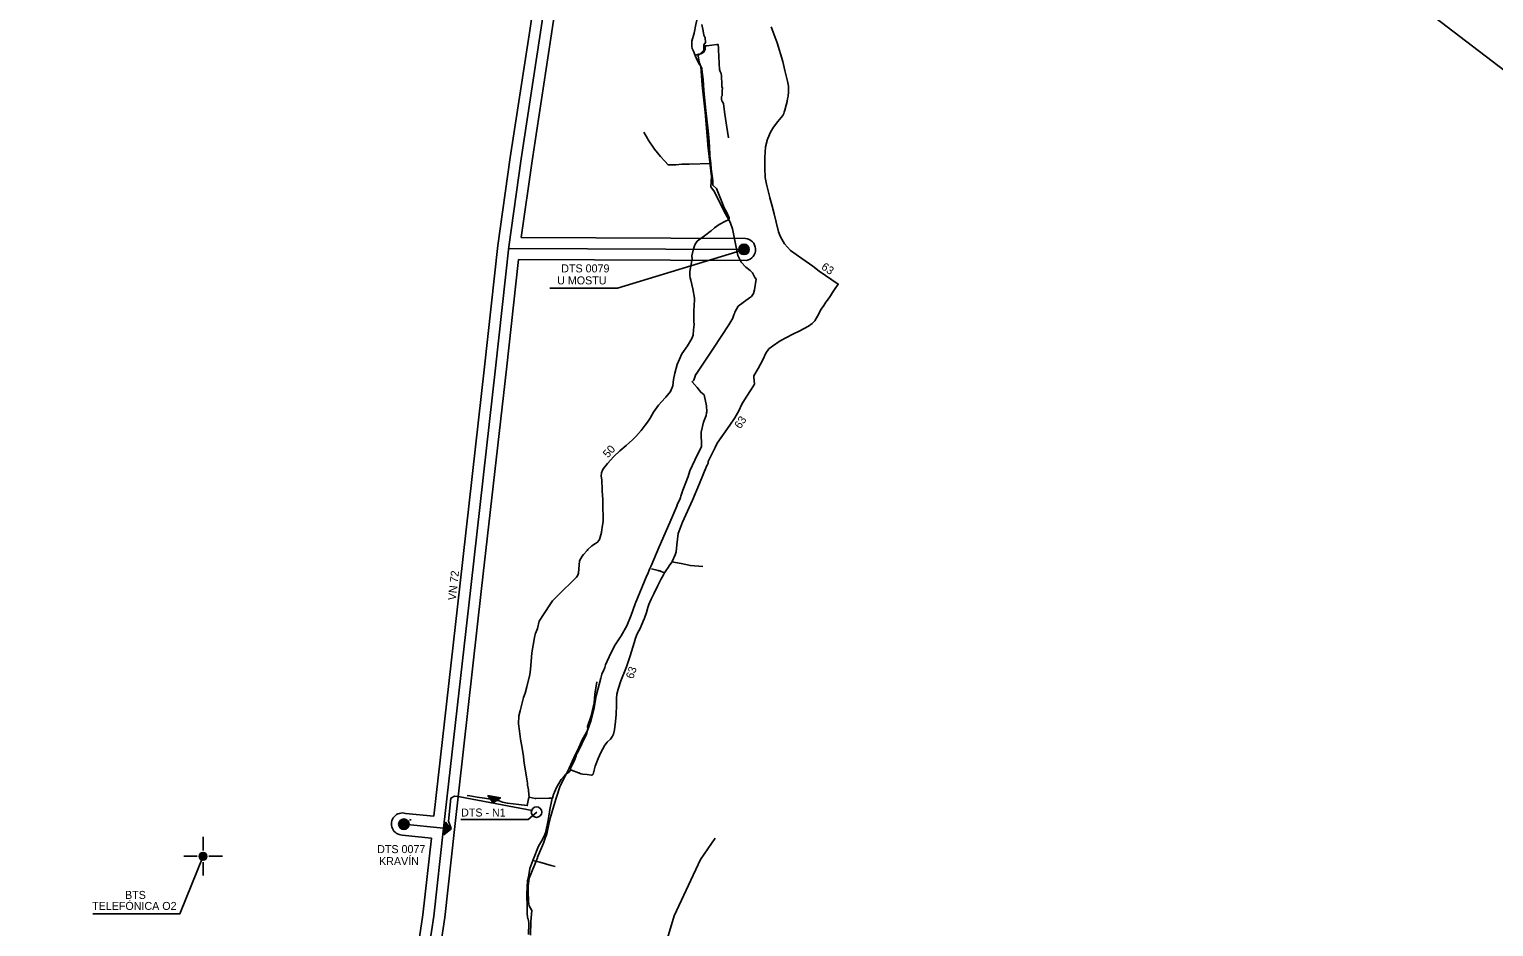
# Model space of a CAD drawing. Extents: x -545241 to -532622, y -1042837 to -1037240.
# Drawn here: x -543118 to -541654, y -1039462 to -1038564 of the extents above; entities that cross this region are included whole.
import ezdxf

# ---------------------------------------------------------------- set-up
doc = ezdxf.new("R2010")
doc.units = 0
for name, color, linetype in [('Vrstva 11', 7, 'Continuous'), ('Vrstva 12', 7, 'Continuous'), ('Vrstva 16', 7, 'Continuous'), ('Vrstva 18', 7, 'Continuous'), ('Vrstva 29', 7, 'Continuous'), ('Vrstva 33', 7, 'Continuous'), ('Vrstva 35', 7, 'Continuous'), ('Vrstva 38', 7, 'Continuous'), ('Vrstva 58', 7, 'Continuous'), ('Vrstva 59', 7, 'Continuous'), ('Vrstva 6', 7, 'Continuous'), ('Vrstva 60', 7, 'Continuous')]:
    doc.layers.add(name, color=color, linetype=linetype)

# ---------------------------------------------------------------- blocks, each defined once
blk = doc.blocks.new('ETRAFN')
at = {"layer": 'Vrstva 6'}
blk.add_circle((0, 0), 7.5, dxfattribs=at)
blk = doc.blocks.new('EKAB')
at = {"layer": 'Vrstva 6'}
for points in [[(9, 9), (9, -9), (0, 0)], [(8, 6.586), (8, -6.586), (1.414, 0)], [(7, 4.172), (7, -4.172), (2.828, 0)], [(6, 1.757), (6, -1.757), (4.243, 0)]]:
    blk.add_lwpolyline(points, close=True, dxfattribs=at)

msp = doc.modelspace()

# ---------------------------------------------------------------- linework, layer by layer
at = {"layer": 'Vrstva 11'}
msp.add_lwpolyline([(-542703.6, -1039363.1), (-542696.2, -1039363.4), (-542699, -1039355.9), (-542696.5, -1039332.9), (-542693, -1039331.1), (-542687.4, -1039331.6), (-542615.2, -1039345.5)], dxfattribs=at)
at = {"layer": 'Vrstva 12'}
for centre, radius in [((-542403.4, -1038784.4), 5.25), ((-542403.4, -1038784.4), 4.55), ((-542403.4, -1038784.4), 3.85), ((-542403.4, -1038784.4), 3.15), ((-542403.4, -1038784.4), 2.45), ((-542403.4, -1038784.4), 1.75), ((-542403.4, -1038784.4), 1.05), ((-542403.4, -1038784.4), 0.35), ((-542743.5, -1039359.1), 5.25), ((-542743.5, -1039359.1), 4.55), ((-542743.5, -1039359.1), 3.85), ((-542743.5, -1039359.1), 3.15), ((-542743.5, -1039359.1), 2.45), ((-542743.5, -1039359.1), 1.75), ((-542743.5, -1039359.1), 1.05), ((-542743.5, -1039359.1), 0.35)]:
    msp.add_circle(centre, radius, dxfattribs=at)
at = {"layer": 'Vrstva 18'}
for points in [[(-542452.1, -1038590.4), (-542454, -1038586.2), (-542455.1, -1038583.7), (-542455.7, -1038581.4), (-542455.5, -1038576.2), (-542453.3, -1038568.1), (-542451.6, -1038559.5), (-542449.6, -1038551.3), (-542449.2, -1038548.5), (-542449.2, -1038545.2), (-542449.2, -1038536.9), (-542449.1, -1038530.4), (-542449, -1038529.2), (-542449, -1038528), (-542449, -1038526.9), (-542448.9, -1038525.6), (-542449, -1038524.8)], [(-542376.1, -1038561.9), (-542370.2, -1038577.8), (-542364.5, -1038596.4), (-542362.4, -1038605.5), (-542359.9, -1038616.2), (-542359, -1038621.2), (-542359, -1038626.8), (-542359.3, -1038631.2), (-542359.8, -1038634), (-542360.2, -1038636.1), (-542360.3, -1038636.5), (-542361.2, -1038640.1), (-542362.5, -1038645.3), (-542363.2, -1038647.2), (-542363.3, -1038647.3), (-542363.4, -1038648.6), (-542364.2, -1038649.9), (-542364.7, -1038650.7), (-542369.7, -1038656.4), (-542373.9, -1038662.1), (-542377, -1038667.3), (-542379.6, -1038673.6), (-542379.7, -1038673.8), (-542379.8, -1038674.1), (-542381.9, -1038681.9), (-542382.7, -1038692.4), (-542382.6, -1038703.2), (-542382.2, -1038712.6), (-542380.8, -1038719.3), (-542378.2, -1038729.9), (-542377.6, -1038732.4), (-542377.5, -1038732.8), (-542377.4, -1038733), (-542375.7, -1038739.9), (-542373.3, -1038748.7), (-542371.2, -1038757.3), (-542368.9, -1038766.7), (-542366.9, -1038772), (-542362.9, -1038778.9), (-542357, -1038785.5), (-542345.7, -1038793.5), (-542334.4, -1038801.2), (-542328.3, -1038806.1), (-542309.1, -1038819.1), (-542312.8, -1038824.6), (-542315, -1038827.6), (-542316.9, -1038830.8), (-542320, -1038835.2), (-542320.2, -1038835.4), (-542321.4, -1038837), (-542323.6, -1038840.6), (-542326.3, -1038844.1), (-542329.9, -1038851.1), (-542332.5, -1038855.7), (-542335.1, -1038858.4), (-542339, -1038861.1), (-542347.7, -1038865.8), (-542354.5, -1038869.2), (-542367.1, -1038875.9), (-542375, -1038881), (-542378.6, -1038883.9), (-542381.7, -1038888), (-542384.6, -1038894.7), (-542389.3, -1038903.4), (-542393.6, -1038910.8), (-542393.5, -1038912.2), (-542392.9, -1038919.1), (-542393, -1038919.2), (-542396.3, -1038924.4), (-542401.2, -1038932), (-542405.4, -1038939.2), (-542408.6, -1038945.9), (-542412.7, -1038952.8), (-542417.6, -1038960.3), (-542430.1, -1038978), (-542432.1, -1038982.4), (-542439.1, -1038996.6), (-542439.2, -1038997.9)], [(-542452.1, -1038590.4), (-542450.7, -1038589.9), (-542448.6, -1038589.3), (-542446.4, -1038588.8), (-542443.7, -1038587.3), (-542442.3, -1038584.2), (-542442.3, -1038580.9), (-542440.6, -1038580.9), (-542430.5, -1038579.6), (-542429.3, -1038579.4), (-542429.2, -1038580.2), (-542428.8, -1038582.7), (-542428.9, -1038586), (-542428.6, -1038590.4), (-542428.1, -1038599.2), (-542428, -1038603.9), (-542427.9, -1038604.7), (-542427.2, -1038606.6), (-542426.2, -1038608.4), (-542426.1, -1038608.6), (-542425.8, -1038611), (-542425.4, -1038619.5), (-542425.4, -1038621.7), (-542425, -1038623.2), (-542425.2, -1038625.7), (-542425.1, -1038629.9), (-542425.3, -1038630.8), (-542425.8, -1038631.5), (-542425.8, -1038634.6), (-542425.7, -1038635.8), (-542424.4, -1038637.3), (-542424, -1038639), (-542422.4, -1038649.3), (-542420.8, -1038660.2), (-542418.9, -1038672.8)], [(-542452.1, -1038590.4), (-542450.1, -1038595.2), (-542448.5, -1038598.4), (-542446.1, -1038601.9), (-542445.7, -1038603.5), (-542445.5, -1038604.6), (-542444.3, -1038614.7), (-542443.7, -1038625.4), (-542442.6, -1038636), (-542441.4, -1038645.7), (-542440.7, -1038654.2), (-542439.7, -1038663), (-542438.6, -1038672.4), (-542438, -1038681.4), (-542437.4, -1038690.6), (-542436.7, -1038698.4)], [(-542436.7, -1038698.4), (-542458.3, -1038699.2), (-542465.6, -1038699.3), (-542471.7, -1038699.7), (-542473.1, -1038699.8), (-542477, -1038699.9), (-542478.7, -1038700), (-542479.3, -1038699.9), (-542482.6, -1038696.3), (-542486.9, -1038691.5), (-542492.8, -1038684.3), (-542499.2, -1038675), (-542500, -1038673.5), (-542503.5, -1038667.2)], [(-542436.7, -1038698.4), (-542436.1, -1038703.9), (-542434.9, -1038713.1), (-542434.7, -1038716.1), (-542434.5, -1038720.3), (-542434.3, -1038720.6), (-542430.8, -1038723.6), (-542424.8, -1038738.5), (-542423.4, -1038742.1), (-542420.5, -1038747.4), (-542418.1, -1038752.7), (-542418.2, -1038753.9), (-542419, -1038755), (-542421.8, -1038756.1), (-542428.2, -1038759.6), (-542433, -1038763), (-542436.3, -1038765.7), (-542437.3, -1038766.5), (-542441.5, -1038769.8), (-542450.1, -1038776.3), (-542451.5, -1038778.1), (-542452.5, -1038780), (-542453.2, -1038781.8), (-542454.2, -1038785.3), (-542455.4, -1038790.8), (-542455.3, -1038793.9), (-542455.5, -1038795.5), (-542457.4, -1038806.6), (-542457.4, -1038810.9), (-542457.1, -1038812.8), (-542456.7, -1038815.3), (-542454.7, -1038823.9), (-542453, -1038833.1), (-542452.8, -1038834.8), (-542453.2, -1038840.3), (-542453.4, -1038846.2), (-542453.5, -1038853.8), (-542453.5, -1038855), (-542453.7, -1038856.6), (-542453.3, -1038859.5), (-542453.9, -1038864.9), (-542454.2, -1038870.1), (-542455.7, -1038873.4), (-542459.9, -1038880.8), (-542465.4, -1038888.9), (-542468, -1038894), (-542470.2, -1038899.6), (-542472.4, -1038908.1), (-542473.8, -1038914.6), (-542474.4, -1038920.7), (-542476.9, -1038926.5), (-542481.6, -1038932.3), (-542482.1, -1038932.8), (-542488.9, -1038940), (-542493.8, -1038947.2), (-542497.3, -1038953), (-542500, -1038957), (-542502.1, -1038960.1), (-542506.1, -1038965.3), (-542511.4, -1038971.5), (-542514.8, -1038974.7), (-542515, -1038974.8), (-542521.3, -1038980.3), (-542527.6, -1038985.9), (-542533.7, -1038991.5), (-542540, -1038998.6), (-542543.9, -1039003.5), (-542544.9, -1039005.2), (-542545.9, -1039007.7), (-542546.1, -1039011), (-542545.7, -1039014.9), (-542545.5, -1039017.9), (-542545.1, -1039021.7), (-542545.2, -1039025.8), (-542544.5, -1039034.6), (-542544.5, -1039044.5), (-542544.3, -1039049.8), (-542544.2, -1039056.2), (-542545.2, -1039062.6), (-542545.5, -1039064.5), (-542545.9, -1039067.4), (-542547.8, -1039074.6), (-542549.8, -1039077.2), (-542551.9, -1039078.6), (-542555.6, -1039080.8), (-542559.6, -1039084.5), (-542560.3, -1039085.3), (-542564, -1039089.5), (-542565.1, -1039091), (-542567.9, -1039095.8), (-542569, -1039108.2), (-542569.4, -1039110.2), (-542571, -1039112), (-542576.2, -1039117.5), (-542584.4, -1039125.4), (-542592.3, -1039133.2), (-542594.7, -1039135.6), (-542597.6, -1039139.6), (-542608.1, -1039156.2), (-542609.9, -1039163.4), (-542611.2, -1039166.7)], [(-542439.2, -1038997.9), (-542439.2, -1038998), (-542440.2, -1039000), (-542440.4, -1039000.4), (-542448, -1039018.6), (-542454.9, -1039035.1), (-542464.8, -1039057), (-542469.3, -1039068.5), (-542470.7, -1039079.7), (-542471.3, -1039086.7), (-542472.1, -1039089.7), (-542475.2, -1039096.6), (-542475.4, -1039096.7), (-542475.4, -1039096.8), (-542475.6, -1039097), (-542478.1, -1039100.9), (-542478.1, -1039100.9), (-542479.2, -1039102.3), (-542481.5, -1039105.8), (-542482.9, -1039107.9), (-542483.9, -1039109.8), (-542486.6, -1039114.5), (-542489.4, -1039120.5), (-542493.4, -1039128.9), (-542496.3, -1039134), (-542498.6, -1039139.4), (-542499.8, -1039143.4), (-542500, -1039143.9), (-542501, -1039147.3), (-542503, -1039153), (-542504.1, -1039156), (-542506.7, -1039161.6), (-542507, -1039162.8), (-542510.3, -1039168.7), (-542511.9, -1039173.1), (-542513.2, -1039177.9), (-542517.3, -1039190.7), (-542521, -1039201.8), (-542526.5, -1039215.8), (-542529.3, -1039224), (-542530.7, -1039229.2), (-542530.9, -1039233.3), (-542530.8, -1039240.2), (-542531.3, -1039249.3), (-542531.9, -1039256.5), (-542532.8, -1039264.7), (-542533.8, -1039269), (-542534.8, -1039271.2), (-542536.8, -1039273.9), (-542539.9, -1039276.6), (-542539.9, -1039276.6), (-542540.3, -1039277), (-542541.5, -1039278.6), (-542542.2, -1039279.6), (-542542.6, -1039280.1), (-542546.6, -1039287.5), (-542549.2, -1039293.3), (-542552.2, -1039300.9), (-542553.6, -1039306.3), (-542554.2, -1039309), (-542555, -1039309.8), (-542556, -1039309.9), (-542560.3, -1039309.4), (-542564.5, -1039309.1), (-542566.7, -1039308.7), (-542568, -1039308), (-542568.5, -1039307.7), (-542568.8, -1039307.6), (-542568.9, -1039307.6), (-542576, -1039305), (-542576.6, -1039304.7)], [(-542444.4, -1039101.6), (-542456.9, -1039100.5), (-542466.3, -1039098.5), (-542475.4, -1039096.7)], [(-542482.9, -1039107.9), (-542486.1, -1039106.3), (-542486.4, -1039106.2), (-542486.9, -1039106.1), (-542487.7, -1039105.9), (-542488, -1039105.8), (-542488.4, -1039105.7), (-542489.2, -1039105.4), (-542496, -1039103.8)], [(-542611.2, -1039166.7), (-542611.6, -1039167.6), (-542611.7, -1039167.8), (-542612.8, -1039172.3), (-542615.4, -1039187.8), (-542615.8, -1039192.1), (-542616.7, -1039204.3), (-542617.6, -1039209.4), (-542620.6, -1039221.9), (-542622.2, -1039228), (-542623.7, -1039232.5), (-542627.3, -1039245.9), (-542628.5, -1039250.8), (-542628.9, -1039258.6), (-542628, -1039266.2), (-542626.9, -1039274.1), (-542625.3, -1039283.2), (-542623.8, -1039291.5), (-542623.8, -1039291.7), (-542623.1, -1039298.1), (-542621.8, -1039305.6), (-542620.5, -1039314.2), (-542619.9, -1039318.2), (-542619.7, -1039319.6), (-542619.4, -1039322.2), (-542619.3, -1039322.5), (-542618.3, -1039331.9)], [(-542576.6, -1039304.7), (-542576.9, -1039304.5), (-542577, -1039304.2), (-542577.1, -1039303.8), (-542576.6, -1039302.7), (-542572.9, -1039295.1), (-542571.3, -1039290.7), (-542570.8, -1039289.1), (-542569.9, -1039287.6), (-542565.4, -1039278.8), (-542561.2, -1039270), (-542559.4, -1039263.6), (-542560, -1039261.3), (-542556.3, -1039250.8), (-542553.3, -1039237.9), (-542552.6, -1039229.2), (-542550.6, -1039216.8)], [(-542576.6, -1039304.7), (-542578.5, -1039307.2), (-542579.9, -1039308.2), (-542581.8, -1039309.5), (-542582.9, -1039310.7), (-542586.1, -1039314.5), (-542590.8, -1039322.5), (-542593.8, -1039329.5), (-542595, -1039333.2)], [(-542618.3, -1039331.9), (-542618.7, -1039333.7), (-542620.1, -1039340.5), (-542628.5, -1039339.5), (-542639.9, -1039338.2), (-542644.9, -1039337.1), (-542648.3, -1039335.6), (-542655.4, -1039334.6), (-542656.8, -1039334.2), (-542662.8, -1039333.2), (-542670.3, -1039332), (-542677.6, -1039330.7), (-542680.1, -1039330.4)], [(-542595, -1039333.2), (-542595.1, -1039333.3), (-542595.4, -1039334.6), (-542597.5, -1039344.4), (-542598.8, -1039353.4), (-542600.1, -1039360.1), (-542601.8, -1039367.7), (-542603.2, -1039370.9), (-542605.9, -1039375.9), (-542608.7, -1039381), (-542613.9, -1039393.7), (-542614.5, -1039395.4), (-542617.6, -1039403.3), (-542619, -1039412.1), (-542619.8, -1039415.7), (-542620.6, -1039428.7), (-542620.1, -1039442.5), (-542620.2, -1039448.4), (-542620, -1039452), (-542619.5, -1039453.2), (-542619.2, -1039453.9), (-542618.8, -1039455.2), (-542618.6, -1039458), (-542618.7, -1039469.2)], [(-542595, -1039333.2), (-542598, -1039333.2), (-542598.2, -1039333.2), (-542598.4, -1039333.2), (-542611.4, -1039333.5), (-542611.6, -1039333.5), (-542611.7, -1039333.5), (-542612.1, -1039333.5), (-542618.3, -1039331.9)], [(-542592.1, -1039401.4), (-542596.2, -1039400.3), (-542607.6, -1039397.2), (-542614.5, -1039395.4)]]:
    msp.add_lwpolyline(points, dxfattribs=at)
at = {"layer": 'Vrstva 33'}
for p, q in [((-542713.5, -1039351), (-542741.7, -1039348.3)), ((-542745.2, -1039370), (-542716, -1039372.9))]:
    msp.add_line(p, q, dxfattribs=at)
for points in [[(-543118, -1037574.6), (-543062.5, -1037656.5), (-542897.8, -1037898.3), (-542760.5, -1038100.5), (-542710.7, -1038175.2), (-542586.1, -1038357.2), (-542618.2, -1038569.9), (-542637.1, -1038692.4), (-542649.5, -1038780.5), (-542662.8, -1038901.9), (-542687.5, -1039121.1), (-542713.5, -1039351)], [(-542626.2, -1038772.5), (-542615.3, -1038695.7), (-542596.5, -1038573.3), (-542563.1, -1038351.9), (-542692.5, -1038162.8), (-542735.4, -1038098.5)], [(-542402, -1038773.4), (-542626.2, -1038772.5)], [(-542721.7, -1039578.9), (-542718.9, -1039560), (-542702.6, -1039452.5), (-542692.9, -1039364.3), (-542665.7, -1039123.5), (-542640.9, -1038904.3), (-542628.9, -1038794.4)], [(-542628.9, -1038794.4), (-542401, -1038795.4)], [(-542716, -1039372.9), (-542724.4, -1039449.6), (-542740.6, -1039556.7), (-542776, -1039795.9), (-542787.3, -1039861.4), (-542796.9, -1039940.9), (-542699.6, -1040093)]]:
    msp.add_lwpolyline(points, dxfattribs=at)
for centre, start, end in [((-542402.9, -1038784.5), 279.8158, 85.5839), ((-542744.8, -1039358.9), 74.027, 267.7876), ((-542738.4, -1039365.6), 79.3713, 86.9725)]:
    msp.add_arc(centre, 11.1, start, end, dxfattribs=at)
at = {"layer": 'Vrstva 35'}
msp.add_lwpolyline([(-542615.5, -1039551.2), (-542566, -1039538.4), (-542513.2, -1039531.6), (-542490.2, -1039507.7), (-542473.2, -1039450.6), (-542446.8, -1039394.4), (-542432.3, -1039373.1)], dxfattribs=at)
at = {"layer": 'Vrstva 38'}
for p, q in [((-542743.6, -1039360), (-542743.6, -1039360)), ((-542743.5, -1039359.1), (-542703.8, -1039363.1))]:
    msp.add_line(p, q, dxfattribs=at)
for points in [[(-542685.4, -1040094.8), (-542785.5, -1039938.3), (-542776.4, -1039863), (-542765.2, -1039797.6), (-542729.7, -1039558.4), (-542713.5, -1039451), (-542703.8, -1039363.1), (-542676.6, -1039122.3), (-542651.9, -1038903.1), (-542638.6, -1038781.9), (-542626.2, -1038694), (-542607.4, -1038571.6), (-542574.6, -1038354.5), (-542701.6, -1038169), (-542751.4, -1038094.3), (-542888.7, -1037892.1), (-543053.4, -1037650.3), (-543107.9, -1037569.9)], [(-542638, -1038783.4), (-542403.4, -1038784.4)]]:
    msp.add_lwpolyline(points, dxfattribs=at)
at = {"layer": 'Vrstva 58'}
for points in [[(-542546.7, -1039213.2), (-542545.7, -1039209.1), (-542543.4, -1039204.8), (-542543, -1039203.4), (-542542.7, -1039202.5), (-542541.9, -1039199.8), (-542536.7, -1039188.2), (-542532.3, -1039179.6), (-542526.3, -1039170.7), (-542520.6, -1039160.6), (-542516.3, -1039150), (-542512.1, -1039138.6), (-542509.9, -1039133.2), (-542502.8, -1039116.2), (-542500.6, -1039110.5), (-542500, -1039109.4), (-542497.7, -1039103.5), (-542496.3, -1039100.7), (-542488.1, -1039081.8), (-542477.5, -1039057.4), (-542470.7, -1039041.2), (-542469.9, -1039038.9), (-542467.7, -1039034.5), (-542467, -1039032.5), (-542466.6, -1039031), (-542464.5, -1039025.1), (-542459.2, -1039011.4), (-542457.5, -1039005.7), (-542452.5, -1038995), (-542445.9, -1038981.6), (-542446.2, -1038967), (-542444, -1038957.3), (-542441.1, -1038950.4), (-542440.8, -1038947.8), (-542440.7, -1038946.9), (-542440.8, -1038940.7), (-542443.3, -1038929.9), (-542446.7, -1038927.2), (-542450.1, -1038922.4), (-542455.3, -1038916.7), (-542453.4, -1038915), (-542451.4, -1038909.2), (-542451.2, -1038909), (-542433.9, -1038883), (-542418.5, -1038859.8), (-542414.5, -1038853.1), (-542414.1, -1038852), (-542414.1, -1038851.8), (-542413.4, -1038849.7), (-542412.8, -1038848.4), (-542412.4, -1038847.3), (-542409.1, -1038841.2), (-542397.9, -1038832.9), (-542395.8, -1038831.4), (-542394, -1038828.4), (-542392.8, -1038824.7), (-542391.1, -1038814.3), (-542392.6, -1038812.6), (-542394.8, -1038807.7), (-542397.3, -1038805.4), (-542401.5, -1038802.2), (-542406.3, -1038797.2), (-542409.4, -1038790.4), (-542414.8, -1038763.9), (-542416.8, -1038758.3), (-542417.3, -1038757.2), (-542418.3, -1038755.5), (-542423.8, -1038745.1), (-542424.5, -1038743.9), (-542433, -1038726.9), (-542436.5, -1038721.9), (-542435.9, -1038711.5), (-542439.4, -1038680.1), (-542439.9, -1038674.9), (-542442.2, -1038647.1), (-542445.1, -1038620.2), (-542446.6, -1038601.5), (-542448.1, -1038597.1), (-542449.1, -1038590.8), (-542443.6, -1038585.3), (-542443.6, -1038580), (-542441.8, -1038577.5), (-542442.2, -1038573), (-542443.7, -1038570.2), (-542444.2, -1038565.8), (-542445.5, -1038559.6)], [(-542546.7, -1039213.2), (-542551.1, -1039230.7), (-542553.4, -1039244.4), (-542556.5, -1039256.2), (-542560, -1039265.3), (-542565.1, -1039274.8), (-542569.5, -1039284.8), (-542572.2, -1039289.8), (-542578.1, -1039303.2), (-542583.9, -1039314.5), (-542587.3, -1039320.6), (-542591.2, -1039333), (-542594.4, -1039344.2), (-542596.4, -1039351.2), (-542598.5, -1039359), (-542600.6, -1039368.8), (-542601.8, -1039372), (-542603.9, -1039378), (-542609.8, -1039392.2), (-542610, -1039392.6), (-542618.2, -1039413), (-542619.1, -1039420.7), (-542619.1, -1039425.5), (-542618.9, -1039436.8), (-542618.1, -1039440.7), (-542615.6, -1039445.3), (-542616.5, -1039456.2), (-542616.8, -1039470.1)]]:
    msp.add_lwpolyline(points, dxfattribs=at)
at = {"layer": 'Vrstva 59'}
for points in [[(-540237.7, -1039677.9), (-540249.9, -1039668.6), (-541016.7, -1039083.3), (-541783.4, -1038498.1), (-542550.2, -1037912.8)], [(-542597.5, -1038823), (-542529.9, -1038823), (-542402.9, -1038784.5)], [(-542686.5, -1039354.4), (-542619.1, -1039354.4), (-542610.4, -1039347.1)]]:
    msp.add_lwpolyline(points, dxfattribs=at)
at = {"layer": 'Vrstva 60'}
for points in [[(-542944.3, -1039371.8), (-542944.3, -1039385.3)], [(-543054.4, -1039448.6), (-542967.4, -1039448.6), (-542944.3, -1039391.2)], [(-542950.1, -1039391.2), (-542963.6, -1039391.2)], [(-542938.4, -1039391.2), (-542924.9, -1039391.2)], [(-542944.3, -1039410.5), (-542944.3, -1039397)]]:
    msp.add_lwpolyline(points, dxfattribs=at)
for radius in [3.87, 2.9, 1.94, 0.968]:
    msp.add_circle((-542944.3, -1039391.2), radius, dxfattribs=at)

# ---------------------------------------------------------------- block references
at = {"layer": 'Vrstva 11', "yscale": 0.7}
for p, xscale, rotation in [((-542654.3, -1039337.8), 0.7, 80.1646931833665), ((-542696.5, -1039364.1), 0.6999999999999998, 172.8355718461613)]:
    msp.add_blockref('EKAB', p, dxfattribs=dict(at, xscale=xscale, rotation=rotation))
at = {"layer": 'Vrstva 29', "xscale": 0.7, "yscale": 0.7}
msp.add_blockref('ETRAFN', (-542610.8, -1039347), dxfattribs=at)

# ---------------------------------------------------------------- texts
at = {"layer": 'Vrstva 16'}
for s, rotation, p in [('63', 326.1387, (-542326.8, -1038803.6)), ('63', 56.7351, (-542407, -1038964.4)), ('50', 48.1067, (-542539.4, -1038993.4)), ('63', 71.5342, (-542514.2, -1039214.4))]:
    msp.add_text(s, height=8, rotation=rotation, dxfattribs=at).set_placement(p)
at = {"layer": 'Vrstva 59'}
for s, p in [('DTS 0079', (-542586.1, -1038807.4)), ('U MOSTU', (-542590.2, -1038819.4)), ('DTS - N1', (-542686.3, -1039351.4)), ('DTS 0077', (-542770.2, -1039388)), ('KRAVÍN', (-542768.3, -1039400))]:
    msp.add_text(s, height=8, dxfattribs=at).set_placement(p)
msp.add_text('VN 72', height=8, rotation=83.6543, dxfattribs=at).set_placement((-542691.6, -1039135.6))
at = {"layer": 'Vrstva 60'}
for s, p in [('TELEFÓNICA O2', (-543055.2, -1039444.8)), ('BTS', (-543022.3, -1039433.8))]:
    msp.add_text(s, height=8, dxfattribs=at).set_placement(p)

doc.saveas('drawing.dxf')
